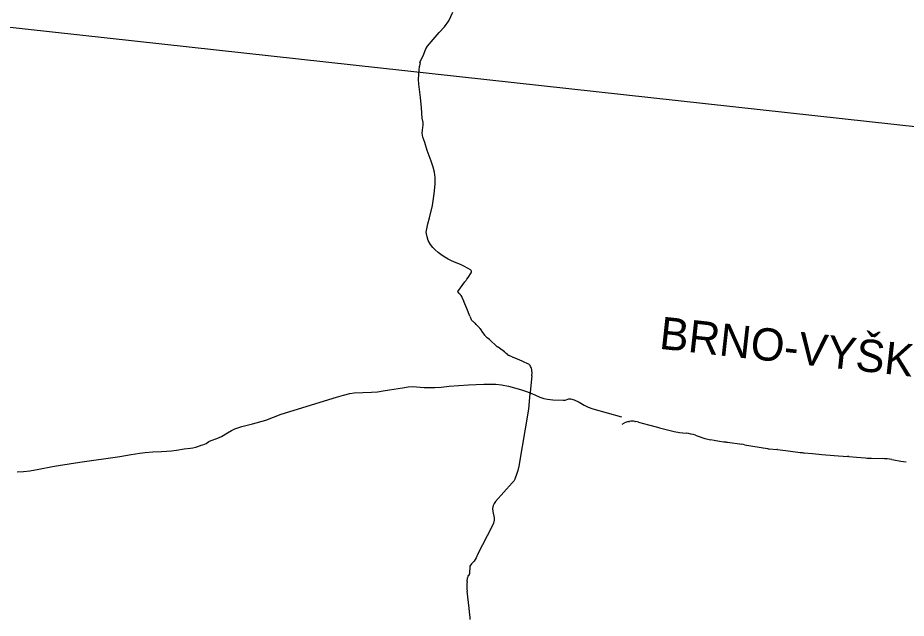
# Model space of a CAD drawing. Extents: x -678204 to -526855, y -1228851 to -1110393.
# Drawn here: x -592047 to -587930, y -1163218 to -1160434 of the extents above; entities that cross this region are included whole.
import ezdxf

# ---------------------------------------------------------------- set-up
doc = ezdxf.new("R2010")
doc.units = 0
for name, color, linetype in [('00_n_cyklo popisy ostatni', 7, 'Continuous'), ('00_n_cyklo studie rekreacni vedlejsi', 7, 'Continuous'), ('00_n_cyklo trasovani rekreacni vedlejsi', 7, 'Continuous'), ('_HELP BIG', 7, 'Continuous')]:
    doc.layers.add(name, color=color, linetype=linetype)

msp = doc.modelspace()

# ---------------------------------------------------------------- linework, layer by layer
at = {"layer": '00_n_cyklo studie rekreacni vedlejsi'}
for p, q in [((-589948.7, -1161603.1), (-589959.3, -1161595.9)), ((-589665.6, -1162094), (-589672.2, -1162169.7)), ((-589246, -1162318.2), (-589235.5, -1162312.2)), ((-589217, -1162306.1), (-589211.9, -1162305.4)), ((-589073.3, -1162335.4), (-589012.1, -1162350.4)), ((-588981.1, -1162356.3), (-588949.3, -1162360.6)), ((-588758, -1162402.2), (-588691.7, -1162411.5)), ((-588678.6, -1162413.5), (-588572.3, -1162431.3)), ((-588565.3, -1162432.2), (-588529, -1162435.7)), ((-588264, -1162463.9), (-588202.4, -1162467.8))]:
    msp.add_line(p, q, dxfattribs=at)
for points in [[(-589959.3, -1161595.9), (-589982.7, -1161583.5), (-589995.6, -1161578.1), (-590022.8, -1161567.3), (-590040.4, -1161559.2), (-590053.1, -1161552.9), (-590075.3, -1161539.6), (-590086, -1161532.2), (-590099, -1161522.7), (-590112.5, -1161510.2), (-590123.5, -1161498.7), (-590134.5, -1161484.8), (-590144.6, -1161466.1), (-590150.4, -1161450.2), (-590153.7, -1161435.8), (-590154.2, -1161428.5), (-590153.4, -1161420.3), (-590146.8, -1161388.9), (-590139.9, -1161361.5), (-590125.9, -1161304.2), (-590118.1, -1161250), (-590112.2, -1161204.8), (-590112.4, -1161174), (-590115.4, -1161149.9), (-590122, -1161127.4), (-590130.7, -1161098.7), (-590149.6, -1161049.4), (-590161.3, -1161012.5), (-590169.4, -1160987.6), (-590172.4, -1160969.3), (-590171.5, -1160955.5), (-590168.9, -1160930.2), (-590168.3, -1160919), (-590172.4, -1160900), (-590175.8, -1160851.4), (-590181.3, -1160804.1), (-590189.2, -1160742.1), (-590189.5, -1160720), (-590187.7, -1160675.9), (-590186, -1160659.9), (-590180.7, -1160644.4), (-590183.8, -1160639.4), (-590168.6, -1160610.3), (-590155.6, -1160577.7), (-590147.9, -1160565.8), (-590121.5, -1160534.1), (-590093.6, -1160502), (-590070.2, -1160476.1), (-590049.6, -1160448.7), (-590031.3, -1160407.4)], [(-589965.4, -1161646.2), (-589960, -1161638.8), (-589946, -1161616.7)], [(-590008, -1161702.8), (-589975.4, -1161658)], [(-590008, -1161702.8), (-590008, -1161702.8)], [(-590001.7, -1161711.7), (-590008, -1161702.8)], [(-589992.6, -1161721.9), (-589999.7, -1161714.2)], [(-589982.3, -1161744.8), (-589987.6, -1161730.2)], [(-589952.7, -1161817.7), (-589966.8, -1161782.1), (-589980.7, -1161748.8)], [(-589927.6, -1161850.9), (-589937.1, -1161842.7), (-589940.1, -1161840.1), (-589942.5, -1161837.4), (-589945.7, -1161831.9)], [(-589907.5, -1161871.4), (-589916.1, -1161861.8), (-589922.1, -1161856), (-589926.1, -1161852.2)], [(-589881.1, -1161907.7), (-589891.6, -1161892.7), (-589900.2, -1161881.2), (-589903.4, -1161876.6)], [(-589857.8, -1161929.2), (-589861.6, -1161926), (-589871.4, -1161918.2)], [(-589829.7, -1161955.1), (-589856.1, -1161930.7)], [(-589816.4, -1161964.8), (-589823.6, -1161960)], [(-589792.2, -1161983), (-589814, -1161966.5)], [(-589777.1, -1161995.1), (-589783.7, -1161990.3), (-589789.6, -1161985.1)], [(-589763.6, -1162002.8), (-589769.6, -1161999.8)], [(-589755.8, -1162006.7), (-589763.1, -1162003)], [(-589709.9, -1162026.5), (-589741.5, -1162013), (-589749.6, -1162009.6)], [(-589683, -1162038.5), (-589704.2, -1162028.9), (-589709.9, -1162026.5)], [(-589666.6, -1162059.2), (-589670.8, -1162050.5)], [(-589665.6, -1162094), (-589664, -1162080.1), (-589664.2, -1162069.6)], [(-592020.6, -1162537.6), (-591990.7, -1162534), (-591949.6, -1162527), (-591886.6, -1162515.1), (-591858.3, -1162509.3), (-591809.5, -1162501.8), (-591760.4, -1162494.9), (-591574.8, -1162468), (-591522, -1162459.4), (-591481.6, -1162452.4), (-591456.5, -1162449.2), (-591421.9, -1162446.6), (-591381.8, -1162444.6), (-591357.3, -1162443.3), (-591335.3, -1162441.2), (-591312.4, -1162438.2), (-591276.7, -1162432.8), (-591246.3, -1162429.6), (-591235.5, -1162428.2), (-591222.3, -1162425), (-591207.6, -1162420.2), (-591197.8, -1162415.8), (-591189.7, -1162413.6), (-591174.5, -1162407.5), (-591161.2, -1162399.1), (-591151.5, -1162394.6), (-591124.7, -1162384.9), (-591103.7, -1162374.8), (-591075.3, -1162358.9), (-591056.1, -1162347.3), (-591041.7, -1162340), (-591009.2, -1162329.8), (-590959.6, -1162317.4), (-590897.7, -1162299.1), (-590826.5, -1162272.5), (-590570.5, -1162193.1), (-590537.5, -1162183.4), (-590509, -1162176.5), (-590488.6, -1162173.4), (-590408, -1162170.4), (-590380, -1162168.1), (-590353.8, -1162164.2), (-590325.1, -1162159.5), (-590264.7, -1162149.3), (-590238.5, -1162145.1), (-590217.7, -1162143.1), (-590163.9, -1162147.5), (-590141.5, -1162149), (-590113.9, -1162148.7), (-590084.7, -1162146.3), (-590047.9, -1162142.5)], [(-590047.9, -1162142.5), (-589959.1, -1162135.7), (-589887.7, -1162133.3), (-589831, -1162133.5), (-589804.9, -1162136.2), (-589772.9, -1162141.5), (-589717.5, -1162157.6), (-589684.9, -1162168.5), (-589650.7, -1162183), (-589627.4, -1162193.7), (-589609.3, -1162200), (-589591.5, -1162202.6), (-589567.2, -1162205.3), (-589519.2, -1162206.8), (-589510.3, -1162206.6), (-589493.1, -1162200.5), (-589485.5, -1162200.4), (-589468.5, -1162205.7), (-589445.8, -1162216.8), (-589422.9, -1162230.9), (-589403.7, -1162239.5), (-589381.4, -1162246.4), (-589249.8, -1162283.6)], [(-589672.2, -1162169.7), (-589674.6, -1162176.4), (-589680.9, -1162248.2)], [(-589680.9, -1162248.2), (-589725.6, -1162512.3), (-589729.1, -1162533.7), (-589733.9, -1162547.6), (-589743.6, -1162574), (-589748, -1162582.4), (-589755.4, -1162590.7), (-589834, -1162677.4), (-589840.1, -1162686.1), (-589844.3, -1162694.6), (-589846.9, -1162709.3), (-589845, -1162723.8)], [(-589188.1, -1162305.3), (-589186.8, -1162305.5), (-589183.8, -1162305.9)], [(-589170.5, -1162308.6), (-589124.5, -1162321.2), (-589082.8, -1162332.9)], [(-588906.1, -1162369.7), (-588903.8, -1162370.4), (-588862.4, -1162384.1)], [(-588836.4, -1162390.1), (-588819.3, -1162392.6), (-588795, -1162396.3), (-588774.3, -1162399.6)], [(-588525.9, -1162436.1), (-588476.8, -1162442.4), (-588420.5, -1162449.3)], [(-588402.5, -1162451.2), (-588363.6, -1162454.5), (-588320.2, -1162458.2), (-588264, -1162463.9)], [(-588195.5, -1162468.3), (-588159.6, -1162471.4), (-588118.3, -1162475.1)], [(-588102.2, -1162476.1), (-588090, -1162476.6), (-588041.9, -1162477.8)], [(-587995.7, -1162482.5), (-587986.7, -1162484.2), (-587955, -1162489.9), (-587929.7, -1162493.6)], [(-592050.3, -1162539.9), (-592020.6, -1162537.6)], [(-589845, -1162723.8), (-589839.8, -1162751.8), (-589839.5, -1162763.9), (-589842.2, -1162776.6), (-589850.2, -1162793.7), (-589915.1, -1162919.3), (-589922.9, -1162937.2), (-589931.7, -1162953.4), (-589945.1, -1162965.7), (-589951.8, -1162976.3), (-589954.4, -1163012.1), (-589954.6, -1163014.3), (-589955.3, -1163016), (-589958.6, -1163019.3), (-589960.8, -1163022), (-589962, -1163024.7), (-589963, -1163031.4)], [(-589964.8, -1163047), (-589963, -1163031.4)], [(-589964.8, -1163047), (-589963, -1163031.4)], [(-589951.7, -1163203.9), (-589955.5, -1163171.9), (-589964.7, -1163092.7)], [(-589950.2, -1163224.2), (-589950.5, -1163218)]]:
    msp.add_lwpolyline(points, dxfattribs=at)
for centre, radius, start, end in [((-589954.4, -1161611.4), 10, 327.5576, 55.3698), ((-589935, -1161687.3), 50, 135.0578, 144.0338), ((-590005.8, -1161616.7), 50, 315.0578, 323.8204), ((-589981.3, -1161697.3), 25, 215.0352, 222.4695), ((-590011.1, -1161738.8), 25, 20.0932, 42.4695), ((-589888.4, -1161710.4), 100, 200.0932, 202.5812), ((-589859.8, -1161780.8), 100, 201.6371, 210.7423), ((-589960.2, -1161888.8), 50, 47.0916, 49.3591), ((-589944.7, -1161904.8), 50, 34.2624, 41.9029), ((-589840.1, -1161879.2), 50, 214.8433, 231.2831), ((-589890, -1161967.4), 50, 47.2197, 49.8847), ((-589795.7, -1161918.4), 50, 227.2197, 236.1681), ((-589844.2, -1162006.4), 50, 52.856, 56.1681), ((-589822.4, -1162022.9), 50, 49.0424, 52.856), ((-589747.3, -1161955), 50, 233.3281, 243.4729), ((-589808.3, -1162092.2), 100, 63.1663, 63.4729), ((-589710.7, -1161917.5), 100, 243.1663, 247.073), ((-589693.3, -1162061.3), 25, 25.4793, 65.6408), ((-589689.2, -1162070), 25, 0.9792, 25.4793), ((-589653.6, -1162095.3), 12, 173.6434, 176.3643), ((-589210.8, -1162355.7), 50, 97.0826, 119.6347), ((-589199.6, -1162404.7), 100, 83.377, 97.0826), ((-589196.9, -1162405), 100, 74.664, 82.4659), ((-589001.8, -1162044), 300, 254.3418, 256.2245), ((-588940.7, -1162059), 300, 256.2245, 262.2559), ((-588989.7, -1162657.8), 300, 73.8247, 82.2559), ((-588815.4, -1162241.6), 150, 251.7291, 261.9338), ((-588688.4, -1161907), 500, 260.1002, 261.9975), ((-588761.3, -1162906.6), 500, 80.4829, 81.9975), ((-588555.7, -1162332.7), 100, 260.4829, 264.4918), ((-588538.6, -1162535.3), 100, 82.683, 84.4918), ((-588359.8, -1161953), 500, 263.029, 265.1036), ((-588221.2, -1162767.2), 300, 85.0991, 86.4173), ((-588091.3, -1162176.3), 300, 264.8478, 267.9289), ((-588049.4, -1162777.7), 300, 79.6863, 88.5651), ((-589766.1, -1163069.5), 200, 173.5309, 186.6671), ((-589766.1, -1163069.5), 200, 173.5309, 186.6671), ((-590150.3, -1163227.4), 200, 2.6801, 6.7516)]:
    msp.add_arc(centre, radius, start, end, dxfattribs=at)
at = {"layer": '00_n_cyklo trasovani rekreacni vedlejsi'}
for p, q in [((-589948.7, -1161603.1), (-589959.3, -1161595.9)), ((-589665.6, -1162094), (-589672.2, -1162169.7)), ((-589246, -1162318.2), (-589235.5, -1162312.2)), ((-589217, -1162306.1), (-589211.9, -1162305.4)), ((-589073.3, -1162335.4), (-589012.1, -1162350.4)), ((-588981.1, -1162356.3), (-588949.3, -1162360.6)), ((-588758, -1162402.2), (-588691.7, -1162411.5)), ((-588678.6, -1162413.5), (-588572.3, -1162431.3)), ((-588565.3, -1162432.2), (-588529, -1162435.7)), ((-588264, -1162463.9), (-588202.4, -1162467.8))]:
    msp.add_line(p, q, dxfattribs=at)
for points in [[(-589959.3, -1161595.9), (-589982.7, -1161583.5), (-589995.6, -1161578.1), (-590022.8, -1161567.3), (-590040.4, -1161559.2), (-590053.1, -1161552.9), (-590075.3, -1161539.6), (-590086, -1161532.2), (-590099, -1161522.7), (-590112.5, -1161510.2), (-590123.5, -1161498.7), (-590134.5, -1161484.8), (-590144.6, -1161466.1), (-590150.4, -1161450.2), (-590153.7, -1161435.8), (-590154.2, -1161428.5), (-590153.4, -1161420.3), (-590146.8, -1161388.9), (-590139.9, -1161361.5), (-590125.9, -1161304.2), (-590118.1, -1161250), (-590112.2, -1161204.8), (-590112.4, -1161174), (-590115.4, -1161149.9), (-590122, -1161127.4), (-590130.7, -1161098.7), (-590149.6, -1161049.4), (-590161.3, -1161012.5), (-590169.4, -1160987.6), (-590172.4, -1160969.3), (-590171.5, -1160955.5), (-590168.9, -1160930.2), (-590168.3, -1160919), (-590172.4, -1160900), (-590175.8, -1160851.4), (-590181.3, -1160804.1), (-590189.2, -1160742.1), (-590189.5, -1160720), (-590187.7, -1160675.9), (-590186, -1160659.9), (-590180.7, -1160644.4), (-590183.8, -1160639.4), (-590168.6, -1160610.3), (-590155.6, -1160577.7), (-590147.9, -1160565.8), (-590121.5, -1160534.1), (-590093.6, -1160502), (-590070.2, -1160476.1), (-590049.6, -1160448.7), (-590031.3, -1160407.4)], [(-589965.4, -1161646.2), (-589960, -1161638.8), (-589946, -1161616.7)], [(-590008, -1161702.8), (-589975.4, -1161658)], [(-590008, -1161702.8), (-590008, -1161702.8)], [(-590001.7, -1161711.7), (-590008, -1161702.8)], [(-589992.6, -1161721.9), (-589999.7, -1161714.2)], [(-589982.3, -1161744.8), (-589987.6, -1161730.2)], [(-589952.7, -1161817.7), (-589966.8, -1161782.1), (-589980.7, -1161748.8)], [(-589927.6, -1161850.9), (-589937.1, -1161842.7), (-589940.1, -1161840.1), (-589942.5, -1161837.4), (-589945.7, -1161831.9)], [(-589907.5, -1161871.4), (-589916.1, -1161861.8), (-589922.1, -1161856), (-589926.1, -1161852.2)], [(-589881.1, -1161907.7), (-589891.6, -1161892.7), (-589900.2, -1161881.2), (-589903.4, -1161876.6)], [(-589857.8, -1161929.2), (-589861.6, -1161926), (-589871.4, -1161918.2)], [(-589829.7, -1161955.1), (-589856.1, -1161930.7)], [(-589816.4, -1161964.8), (-589823.6, -1161960)], [(-589792.2, -1161983), (-589814, -1161966.5)], [(-589777.1, -1161995.1), (-589783.7, -1161990.3), (-589789.6, -1161985.1)], [(-589763.6, -1162002.8), (-589769.6, -1161999.8)], [(-589755.8, -1162006.7), (-589763.1, -1162003)], [(-589709.9, -1162026.5), (-589741.5, -1162013), (-589749.6, -1162009.6)], [(-589683, -1162038.5), (-589704.2, -1162028.9), (-589709.9, -1162026.5)], [(-589666.6, -1162059.2), (-589670.8, -1162050.5)], [(-589665.6, -1162094), (-589664, -1162080.1), (-589664.2, -1162069.6)], [(-592020.6, -1162537.6), (-591990.7, -1162534), (-591949.6, -1162527), (-591886.6, -1162515.1), (-591858.3, -1162509.3), (-591809.5, -1162501.8), (-591760.4, -1162494.9), (-591574.8, -1162468), (-591522, -1162459.4), (-591481.6, -1162452.4), (-591456.5, -1162449.2), (-591421.9, -1162446.6), (-591381.8, -1162444.6), (-591357.3, -1162443.3), (-591335.3, -1162441.2), (-591312.4, -1162438.2), (-591276.7, -1162432.8), (-591246.3, -1162429.6), (-591235.5, -1162428.2), (-591222.3, -1162425), (-591207.6, -1162420.2), (-591197.8, -1162415.8), (-591189.7, -1162413.6), (-591174.5, -1162407.5), (-591161.2, -1162399.1), (-591151.5, -1162394.6), (-591124.7, -1162384.9), (-591103.7, -1162374.8), (-591075.3, -1162358.9), (-591056.1, -1162347.3), (-591041.7, -1162340), (-591009.2, -1162329.8), (-590959.6, -1162317.4), (-590897.7, -1162299.1), (-590826.5, -1162272.5), (-590570.5, -1162193.1), (-590537.5, -1162183.4), (-590509, -1162176.5), (-590488.6, -1162173.4), (-590408, -1162170.4), (-590380, -1162168.1), (-590353.8, -1162164.2), (-590325.1, -1162159.5), (-590264.7, -1162149.3), (-590238.5, -1162145.1), (-590217.7, -1162143.1), (-590163.9, -1162147.5), (-590141.5, -1162149), (-590113.9, -1162148.7), (-590084.7, -1162146.3), (-590047.9, -1162142.5)], [(-590047.9, -1162142.5), (-589959.1, -1162135.7), (-589887.7, -1162133.3), (-589831, -1162133.5), (-589804.9, -1162136.2), (-589772.9, -1162141.5), (-589717.5, -1162157.6), (-589684.9, -1162168.5), (-589650.7, -1162183), (-589627.4, -1162193.7), (-589609.3, -1162200), (-589591.5, -1162202.6), (-589567.2, -1162205.3), (-589519.2, -1162206.8), (-589510.3, -1162206.6), (-589493.1, -1162200.5), (-589485.5, -1162200.4), (-589468.5, -1162205.7), (-589445.8, -1162216.8), (-589422.9, -1162230.9), (-589403.7, -1162239.5), (-589381.4, -1162246.4), (-589249.8, -1162283.6)], [(-589672.2, -1162169.7), (-589674.6, -1162176.4), (-589680.9, -1162248.2)], [(-589680.9, -1162248.2), (-589725.6, -1162512.3), (-589729.1, -1162533.7), (-589733.9, -1162547.6), (-589743.6, -1162574), (-589748, -1162582.4), (-589755.4, -1162590.7), (-589834, -1162677.4), (-589840.1, -1162686.1), (-589844.3, -1162694.6), (-589846.9, -1162709.3), (-589845, -1162723.8)], [(-589188.1, -1162305.3), (-589186.8, -1162305.5), (-589183.8, -1162305.9)], [(-589170.5, -1162308.6), (-589124.5, -1162321.2), (-589082.8, -1162332.9)], [(-588906.1, -1162369.7), (-588903.8, -1162370.4), (-588862.4, -1162384.1)], [(-588836.4, -1162390.1), (-588819.3, -1162392.6), (-588795, -1162396.3), (-588774.3, -1162399.6)], [(-588525.9, -1162436.1), (-588476.8, -1162442.4), (-588420.5, -1162449.3)], [(-588402.5, -1162451.2), (-588363.6, -1162454.5), (-588320.2, -1162458.2), (-588264, -1162463.9)], [(-588195.5, -1162468.3), (-588159.6, -1162471.4), (-588118.3, -1162475.1)], [(-588102.2, -1162476.1), (-588090, -1162476.6), (-588041.9, -1162477.8)], [(-587995.7, -1162482.5), (-587986.7, -1162484.2), (-587955, -1162489.9), (-587929.7, -1162493.6)], [(-592050.3, -1162539.9), (-592020.6, -1162537.6)], [(-589845, -1162723.8), (-589839.8, -1162751.8), (-589839.5, -1162763.9), (-589842.2, -1162776.6), (-589850.2, -1162793.7), (-589915.1, -1162919.3), (-589922.9, -1162937.2), (-589931.7, -1162953.4), (-589945.1, -1162965.7), (-589951.8, -1162976.3), (-589954.4, -1163012.1), (-589954.6, -1163014.3), (-589955.3, -1163016), (-589958.6, -1163019.3), (-589960.8, -1163022), (-589962, -1163024.7), (-589963, -1163031.4)], [(-589964.8, -1163047), (-589963, -1163031.4)], [(-589964.8, -1163047), (-589963, -1163031.4)], [(-589951.7, -1163203.9), (-589955.5, -1163171.9), (-589964.7, -1163092.7)], [(-589950.2, -1163224.2), (-589950.5, -1163218)]]:
    msp.add_lwpolyline(points, dxfattribs=at)
for centre, radius, start, end in [((-589954.4, -1161611.4), 10, 327.5576, 55.3698), ((-589935, -1161687.3), 50, 135.0578, 144.0338), ((-590005.8, -1161616.7), 50, 315.0578, 323.8204), ((-589981.3, -1161697.3), 25, 215.0352, 222.4695), ((-590011.1, -1161738.8), 25, 20.0932, 42.4695), ((-589888.4, -1161710.4), 100, 200.0932, 202.5812), ((-589859.8, -1161780.8), 100, 201.6371, 210.7423), ((-589960.2, -1161888.8), 50, 47.0916, 49.3591), ((-589944.7, -1161904.8), 50, 34.2624, 41.9029), ((-589840.1, -1161879.2), 50, 214.8433, 231.2831), ((-589890, -1161967.4), 50, 47.2197, 49.8847), ((-589795.7, -1161918.4), 50, 227.2197, 236.1681), ((-589844.2, -1162006.4), 50, 52.856, 56.1681), ((-589822.4, -1162022.9), 50, 49.0424, 52.856), ((-589747.3, -1161955), 50, 233.3281, 243.4729), ((-589808.3, -1162092.2), 100, 63.1663, 63.4729), ((-589710.7, -1161917.5), 100, 243.1663, 247.073), ((-589693.3, -1162061.3), 25, 25.4793, 65.6408), ((-589689.2, -1162070), 25, 0.9792, 25.4793), ((-589653.6, -1162095.3), 12, 173.6434, 176.3643), ((-589210.8, -1162355.7), 50, 97.0826, 119.6347), ((-589199.6, -1162404.7), 100, 83.377, 97.0826), ((-589196.9, -1162405), 100, 74.664, 82.4659), ((-589001.8, -1162044), 300, 254.3418, 256.2245), ((-588940.7, -1162059), 300, 256.2245, 262.2559), ((-588989.7, -1162657.8), 300, 73.8247, 82.2559), ((-588815.4, -1162241.6), 150, 251.7291, 261.9338), ((-588688.4, -1161907), 500, 260.1002, 261.9975), ((-588761.3, -1162906.6), 500, 80.4829, 81.9975), ((-588555.7, -1162332.7), 100, 260.4829, 264.4918), ((-588538.6, -1162535.3), 100, 82.683, 84.4918), ((-588359.8, -1161953), 500, 263.029, 265.1036), ((-588221.2, -1162767.2), 300, 85.0991, 86.4173), ((-588091.3, -1162176.3), 300, 264.8478, 267.9289), ((-588049.4, -1162777.7), 300, 79.6863, 88.5651), ((-589766.1, -1163069.5), 200, 173.5309, 186.6671), ((-589766.1, -1163069.5), 200, 173.5309, 186.6671), ((-590150.3, -1163227.4), 200, 2.6801, 6.7516)]:
    msp.add_arc(centre, radius, start, end, dxfattribs=at)
at = {"layer": '_HELP BIG'}
msp.add_lwpolyline([(-598180, -1159809.1), (-595073.9, -1131521.8), (-574928.9, -1133733.9), (-578035.1, -1162021.2)], close=True, dxfattribs=at)

# ---------------------------------------------------------------- texts
at = {"layer": '00_n_cyklo popisy ostatni'}
msp.add_text('BRNO-VYŠKOV', height=150, rotation=353.6836, dxfattribs=at).set_placement((-589078.1, -1161968.1))

doc.saveas('drawing.dxf')
